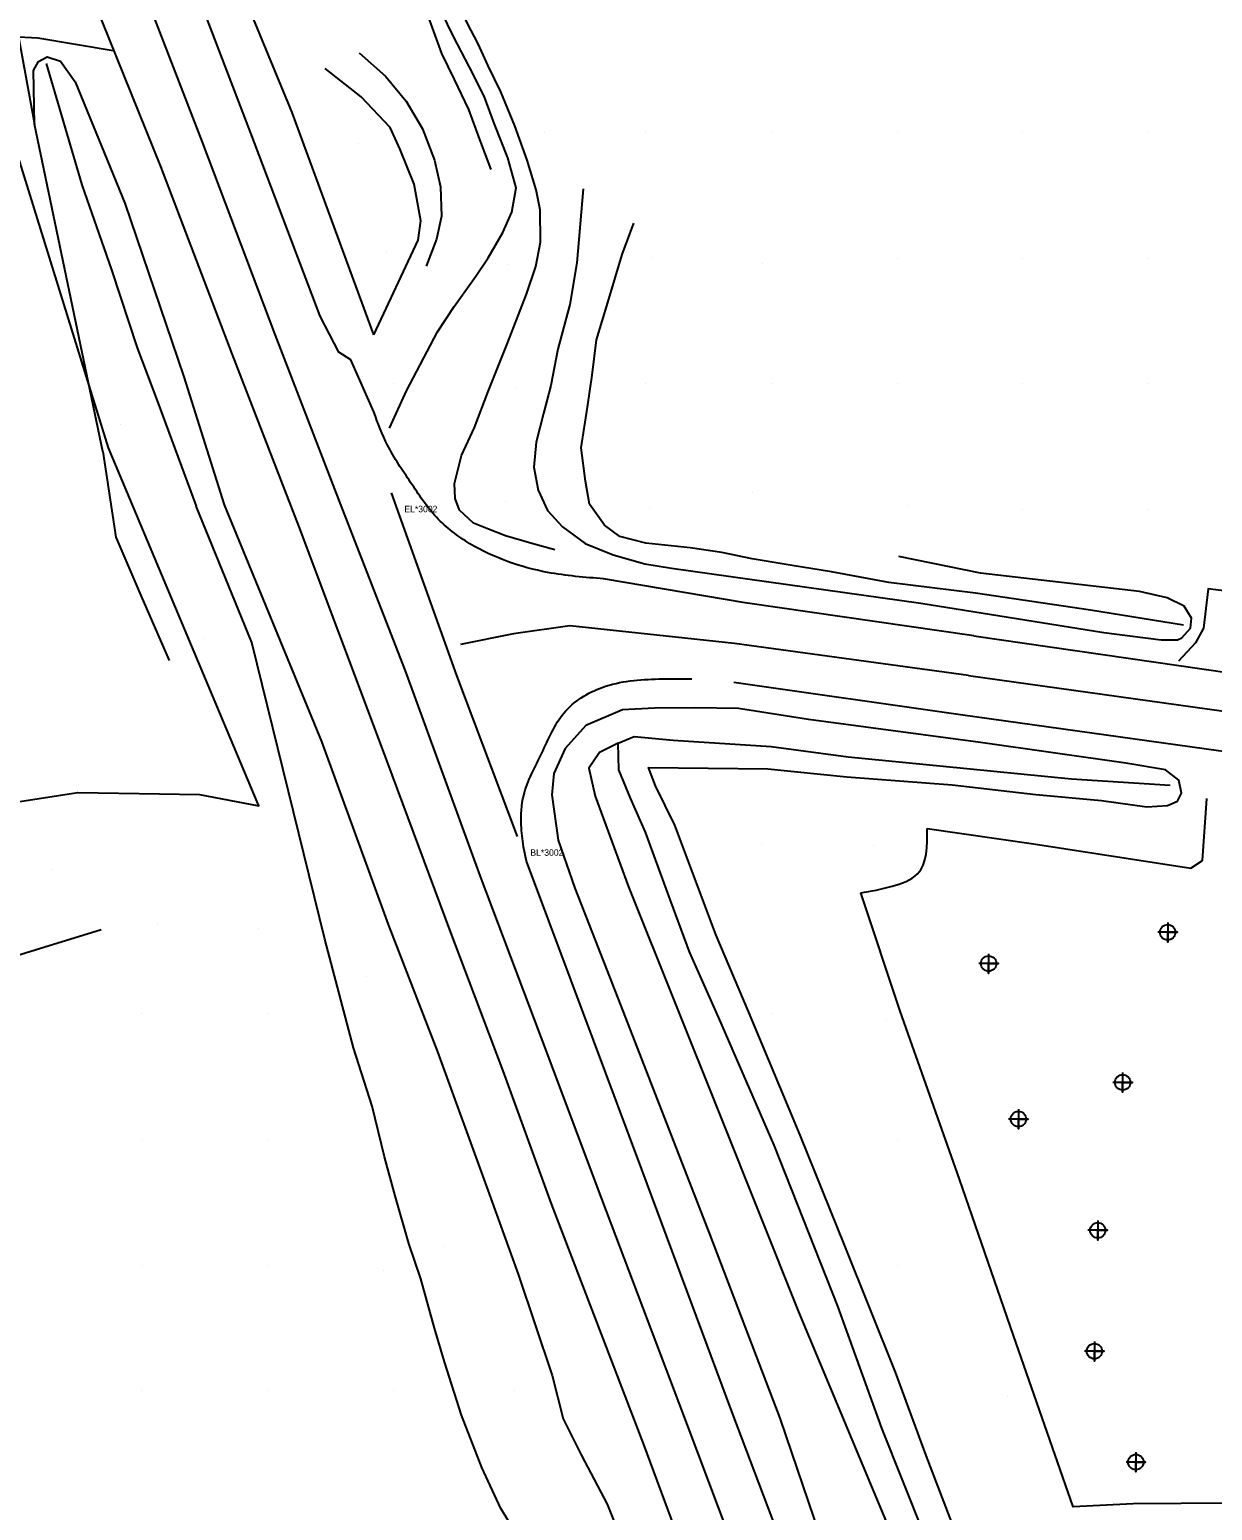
# Model space of a CAD drawing. Extents: x 524772 to 528246, y 273285 to 283088.
# Drawn here: x 527837.2 to 527928.9, y 274106.4 to 274221.1 of the extents above; entities that cross this region are included whole.
import ezdxf

# ---------------------------------------------------------------- set-up
doc = ezdxf.new("R2010")
doc.units = 0
for name, color, linetype in [('Exist DTM Crownline', 7, 'Continuous'), ('Exist DTM Regular Point CELL', 7, 'Continuous'), ('Exist Roads EOP', 7, 'Continuous'), ('Exist Roads EOT', 7, 'Continuous'), ('Exist Roads EOT Cogo Comment', 7, 'Continuous'), ('Old_Level_12', 7, 'Continuous'), ('PH Exist DTM Breakline', 7, 'Continuous'), ('PH Exist DTM Point', 7, 'Continuous')]:
    doc.layers.add(name, color=color, linetype=linetype)

# ---------------------------------------------------------------- blocks, each defined once
blk = doc.blocks.new('EXIST DTM REGULAR POINT')
at = {"layer": 'Exist DTM Regular Point CELL'}
blk.add_lwpolyline([(0, 0.00152), (0, -0.00152), (0, 0), (0.00152, 0), (-0.00152, 0)], dxfattribs=at)
blk.add_circle((0, 0), 0.00119, dxfattribs=at)

msp = doc.modelspace()

# ---------------------------------------------------------------- linework, layer by layer
at = {"layer": 'Exist DTM Crownline'}
for p, q in [((527909.99, 274171.09), (527891.85, 274173.57)), ((527881.22, 274131.5), (527877.32, 274141.9))]:
    msp.add_line(p, q, dxfattribs=at)
for points in [[(527877.32, 274141.9), (527872.16, 274155.51), (527866.36, 274171.44), (527861.32, 274184.4), (527856.24, 274197.5), (527850.61, 274212.41), (527845.36, 274225.99), (527840.1, 274239.58), (527834.55, 274253.77), (527829.3, 274267.02), (527823.63, 274281.27), (527818.21, 274295.07), (527812.62, 274309.15), (527807.09, 274323.12)], [(527891.85, 274173.57), (527879.09, 274174.95), (527874.72, 274174.33), (527870.62, 274173.49)], [(527909.99, 274171.09), (527929.8, 274168.32), (527941.69, 274166.67)], [(527923.71, 274019.28), (527916.64, 274037.99), (527909.48, 274056.66), (527902.42, 274075.37), (527895.35, 274094.08), (527888.28, 274112.79), (527881.22, 274131.5)]]:
    msp.add_lwpolyline(points, dxfattribs=at)
at = {"layer": 'Exist Roads EOP'}
for p, q in [((527892.69, 274176.71), (527881.71, 274178.58)), ((527910.42, 274174.16), (527892.69, 274176.71)), ((527909.57, 274168.02), (527891.81, 274170.56)), ((527884.68, 274132.81), (527880.92, 274142.82)), ((527877.66, 274130.16), (527873.92, 274140.45))]:
    msp.add_line(p, q, dxfattribs=at)
for points in [[(527863.89, 274191.51), (527862.12, 274195.56), (527861.19, 274196.14), (527859.74, 274198.94), (527854.35, 274213.12), (527848.92, 274227.38), (527843.58, 274240.81), (527838, 274255.12), (527832.68, 274268.57), (527827.21, 274282.4), (527821.56, 274296.66), (527815.92, 274310.87), (527810.35, 274324.86), (527804.78, 274338.91), (527799.29, 274352.72), (527793.54, 274366.95), (527787.87, 274381.23), (527782.28, 274395.33), (527776.62, 274409.52), (527770.97, 274423.52), (527765.47, 274437.47), (527760, 274451.08), (527754.4, 274465.08), (527748.73, 274479.07)], [(527873.92, 274140.45), (527869.86, 274151.18), (527864.48, 274165.61), (527858.1, 274182.62), (527852.91, 274196.02), (527847.38, 274210.53), (527841.71, 274224.63), (527836.64, 274238.36), (527831.12, 274252.6), (527825.69, 274266.18), (527820.35, 274279.64), (527814.69, 274293.96), (527808.82, 274308.77), (527803.4, 274322.05)], [(527910.42, 274174.16), (527930.22, 274171.3), (527942.12, 274169.74)], [(527941.29, 274163.79), (527929.37, 274165.25), (527909.57, 274168.02)], [(527906.8, 274159.23), (527915.04, 274158.04), (527927.23, 274156.17), (527928.14, 274156.75), (527928.47, 274161.57)], [(527906.8, 274159.23), (527915.04, 274158.04), (527927.23, 274156.17), (527928.14, 274156.75), (527928.47, 274161.57)], [(527880.92, 274142.82), (527875.74, 274156.69), (527875.5, 274157.82)], [(527945.6, 274107.21), (527933.94, 274106.99), (527922.76, 274106.9), (527918.11, 274106.67), (527913.48, 274119.96), (527909.29, 274132.05), (527904.7, 274145.08), (527901.64, 274154.24)], [(527945.6, 274107.21), (527933.94, 274106.99), (527922.76, 274106.9), (527918.11, 274106.67), (527913.48, 274119.96), (527909.29, 274132.05), (527904.7, 274145.08), (527901.64, 274154.24)], [(527927.17, 274020.59), (527919.92, 274039.22), (527912.85, 274057.93), (527905.78, 274076.65), (527898.72, 274095.36), (527891.65, 274114.07), (527884.68, 274132.81)], [(527920.25, 274017.97), (527912.99, 274036.61), (527906.11, 274055.39), (527898.95, 274074.07), (527891.79, 274092.74), (527884.82, 274111.49), (527877.66, 274130.16)]]:
    msp.add_lwpolyline(points, dxfattribs=at)
for points in [[(527881.71, 274178.58), (527877.37, 274179.08), (527874.25, 274179.93), (527871.35, 274181.3), (527868.75, 274183.35), (527866.75, 274186.05), (527864.96, 274188.94), (527863.89, 274191.51)], [(527875.5, 274157.82), (527875.32, 274159.51), (527875.52, 274161.8), (527876.92, 274165.07), (527878.63, 274168.18), (527881.6, 274170.17), (527885.99, 274170.82), (527888.56, 274170.84)], [(527901.64, 274154.24), (527904.07, 274154.76), (527906.04, 274155.71), (527906.8, 274159.23)], [(527901.64, 274154.24), (527904.07, 274154.76), (527906.04, 274155.71), (527906.8, 274159.23)]]:
    msp.add_spline(points, degree=3, dxfattribs=at)
at = {"layer": 'Exist Roads EOT'}
msp.add_lwpolyline([(527875.03, 274158.62), (527870.34, 274171.09), (527865.26, 274185.24)], dxfattribs=at)
at = {"layer": 'Old_Level_12'}
msp.add_lwpolyline([(527790.41, 274140.76), (527808.09, 274147.58), (527820.7, 274154.72), (527830.77, 274160.45), (527840.94, 274162.02), (527847.27, 274161.91), (527850.38, 274161.86), (527854.98, 274160.99), (527843.32, 274188.73), (527834.36, 274217.55), (527834.17, 274217.65), (527821.77, 274212.77), (527804.33, 274204.71), (527792.62, 274201.51), (527784.15, 274199.26), (527772.83, 274197.49), (527790.39, 274140.96)], dxfattribs=at)
at = {"layer": 'PH Exist DTM Breakline'}
for points in [[(527863.9, 274197.49), (527857.56, 274214.72), (527851.2, 274230.14), (527846, 274240.87), (527842.66, 274248.43), (527840.2, 274254.37)], [(527859.91, 274244.8), (527860.97, 274242.49), (527861.97, 274239.73), (527863.1, 274236.61), (527864.01, 274234.08), (527864.94, 274230.98), (527865.46, 274229.25), (527866.37, 274226.86), (527867.18, 274224.63), (527868.22, 274221.84), (527869.13, 274219.29), (527870.13, 274217.27), (527871.23, 274214.94), (527872.08, 274212.62), (527872.96, 274210.31)], [(527877.94, 274180.84), (527876.15, 274181.32), (527874.1, 274181.91), (527872.78, 274182.42), (527871.63, 274182.89), (527870.55, 274183.89), (527870.19, 274184.81), (527870.14, 274185.98), (527870.68, 274188.13), (527871.69, 274190.31), (527872.75, 274193.09), (527874.27, 274196.83), (527875.72, 274200.64), (527876.46, 274202.77), (527876.83, 274204.67), (527876.78, 274207.16), (527876.48, 274208.72), (527875.78, 274211.02), (527874.83, 274213.69), (527873.74, 274216.31), (527872.77, 274218.34), (527871.99, 274220.04), (527871.15, 274221.61), (527870.13, 274223.79)], [(527865.11, 274190.25), (527866.43, 274193.14), (527868.83, 274197.71), (527870.12, 274199.69), (527871.8, 274202.04), (527872.76, 274203.45), (527873.89, 274205.42), (527874.59, 274207), (527874.94, 274208.88), (527874.29, 274211.2), (527873.24, 274213.8), (527872.44, 274215.98), (527871.3, 274218.24), (527870.08, 274220.6), (527869.13, 274222.51)], [(527836.36, 274220.57), (527837.84, 274220.51), (527843.7, 274219.53)], [(527836.36, 274220.57), (527837.59, 274213.82), (527837.52, 274217.97), (527837.9, 274218.67), (527838.57, 274219.03), (527839.6, 274218.7), (527840.74, 274217.1), (527844.6, 274207.7), (527849.16, 274194.23), (527852.29, 274184.32)], [(527862.75, 274219.33), (527864.79, 274217.52), (527866.41, 274215.6), (527867.68, 274213.45), (527868.6, 274211.01), (527869.07, 274208.96), (527869.13, 274206.68), (527868.76, 274204.91), (527867.95, 274202.81)], [(527838.49, 274218.51), (527841.26, 274209.12), (527843.56, 274202.53), (527845.55, 274196.47), (527847.07, 274192.46), (527850.11, 274184.21)], [(527863.9, 274197.49), (527867.33, 274204.83), (527867.53, 274206.31), (527867.03, 274209.17), (527865.94, 274211.86), (527865.15, 274213.54), (527862.92, 274215.94), (527860.13, 274218.12)], [(527842.89, 274188.45), (527837.59, 274213.82)], [(527880.13, 274208.81), (527879.64, 274203.07), (527879.08, 274199.83), (527878.17, 274196.38), (527877.62, 274193.56), (527877.04, 274191.4), (527876.49, 274189.17), (527876.29, 274187.23), (527876.63, 274185.46), (527877.35, 274183.88), (527878.52, 274182.61), (527880.28, 274181.33), (527882.45, 274180.43), (527884.91, 274179.74), (527886.98, 274179.4), (527906.3, 274176.69), (527920.48, 274174.42), (527924.94, 274173.86), (527926.2, 274173.86), (527926.55, 274174.02), (527927.21, 274174.76), (527927.29, 274175.54), (527926.73, 274176.45), (527925.41, 274177.1), (527923.25, 274177.61), (527910.94, 274179.01), (527904.61, 274180.31)], [(527926.66, 274174.99), (527919.46, 274176.15), (527910.55, 274177.46), (527903.82, 274178.29), (527899.39, 274179.11), (527896.34, 274179.62), (527893.22, 274180.13), (527890.88, 274180.61), (527888.42, 274180.98), (527884.98, 274181.34), (527882.96, 274181.85), (527881.79, 274182.75), (527880.61, 274184.36), (527880.31, 274186.16), (527879.97, 274188.72), (527880.45, 274191.89), (527880.82, 274194.36), (527881.16, 274197.11), (527882.04, 274199.98), (527883.14, 274203.71), (527884.06, 274206.13)], [(527842.89, 274188.45), (527843.9, 274181.8), (527845.84, 274177.29), (527848.04, 274172.25)], [(527888.55, 274069.38), (527880.65, 274092.85), (527878.26, 274099.69), (527877.11, 274101.69), (527875.35, 274103.93), (527873.74, 274106.55), (527872.28, 274109.73), (527870.69, 274113.78), (527869.38, 274117.9), (527868.61, 274120.51), (527867.55, 274124.34), (527866.61, 274127.07), (527865.54, 274130.76), (527864.72, 274133.78), (527863.77, 274137.73), (527862.31, 274142.24), (527860.11, 274150.66), (527854.43, 274173.64), (527850.11, 274184.21)], [(527852.29, 274184.32), (527859.85, 274165.97), (527865.02, 274151.8), (527868.82, 274141.92), (527872.63, 274131.49), (527875.09, 274124.69), (527877.72, 274116.84), (527878.58, 274113.5), (527879.97, 274110.71), (527881.99, 274106.88), (527883.78, 274102.43), (527885.75, 274097.37), (527887.4, 274093.08), (527889.08, 274088.49), (527890.71, 274083.61), (527892.55, 274078.09), (527893.83, 274074.08)], [(527933.53, 274171.12), (527932.31, 274172.45), (527931.54, 274173.72), (527931.43, 274175.19), (527931.58, 274177.41), (527928.57, 274177.81), (527928.22, 274174.77), (527927.6, 274173.63), (527926.29, 274172.2)], [(527920.31, 274161.4), (527923.82, 274160.92), (527925.43, 274161.01), (527926.19, 274161.36), (527926.5, 274161.97), (527926.3, 274162.97), (527925.28, 274163.77), (527922.2, 274164.3), (527910.94, 274165.89), (527897.59, 274167.68), (527892.16, 274168.54), (527888.79, 274168.58), (527885.66, 274168.56), (527883.18, 274168.42), (527880.33, 274167.21), (527878.74, 274165.44), (527877.85, 274163.5), (527877.69, 274161.85), (527878.18, 274158.33), (527879.47, 274154.62), (527883.05, 274145.49), (527889.95, 274127.75), (527895.37, 274113.54), (527899.36, 274101.83)], [(527906.53, 274104.6), (527903.29, 274112.76), (527899.86, 274122.23), (527894.93, 274134.7), (527890.63, 274144.56), (527888.38, 274149.69), (527886.69, 274154.23), (527884.96, 274158.96), (527883.79, 274161.59), (527882.88, 274163.77), (527882.83, 274165.85), (527884.09, 274166.37), (527887.1, 274166.09), (527894.7, 274165.58), (527900.67, 274164.79), (527908.03, 274164.06), (527917.98, 274163.07), (527925.63, 274162.6)], [(527882.83, 274165.85), (527881.38, 274165.13), (527880.56, 274163.92), (527881.05, 274161.74), (527883.64, 274154.71), (527890.78, 274136.91), (527896.81, 274121.78), (527905.08, 274102), (527906.08, 274099.58), (527906.31, 274098.34), (527907.16, 274096.65), (527908.44, 274095.21), (527909.66, 274094.27), (527911.2, 274094.08)], [(527909.04, 274104.58), (527906.72, 274110.66), (527904.34, 274117.11), (527900.42, 274126.9), (527896.94, 274135.47), (527892.94, 274145.06), (527890.41, 274151.03), (527887.22, 274159.49), (527885.73, 274162.53), (527885.19, 274163.97), (527894.45, 274163.85), (527900.56, 274163.24), (527908.74, 274162.61), (527915.21, 274161.86), (527920.31, 274161.4)], [(527788.88, 274132.45), (527821.92, 274144.25), (527829.01, 274147.01), (527833.77, 274148.64), (527837.64, 274149.82), (527842.77, 274151.4)]]:
    msp.add_lwpolyline(points, dxfattribs=at)
at = {"layer": 'PH Exist DTM Point'}
for p, q in [((527862.72, 274212.35), (527862.72, 274212.35)), ((527877.15, 274213.2), (527877.15, 274213.2)), ((527884.95, 274213.19), (527884.95, 274213.19)), ((527894.71, 274213.19), (527894.71, 274213.19)), ((527904.46, 274213.19), (527904.46, 274213.19)), ((527914.22, 274213.19), (527914.22, 274213.19)), ((527923.97, 274213.19), (527923.97, 274213.19)), ((527864.86, 274203.85), (527864.86, 274203.85)), ((527874.24, 274202.95), (527874.24, 274202.95)), ((527885.47, 274203.5), (527885.47, 274203.5)), ((527894.05, 274203.02), (527894.05, 274203.02)), ((527904.46, 274203.44), (527904.46, 274203.44)), ((527914.22, 274203.44), (527914.22, 274203.44)), ((527923.97, 274203.44), (527923.97, 274203.44)), ((527865.45, 274193.69), (527865.45, 274193.69)), ((527874.92, 274193.43), (527874.92, 274193.43)), ((527884.95, 274193.69), (527884.95, 274193.69)), ((527894.71, 274193.69), (527894.71, 274193.69)), ((527904.46, 274193.69), (527904.46, 274193.69)), ((527914.22, 274193.69), (527914.22, 274193.69)), ((527923.97, 274193.69), (527923.97, 274193.69)), ((527844.28, 274190.56), (527844.28, 274190.56)), ((527874.14, 274184.61), (527874.14, 274184.61)), ((527893.27, 274185.3), (527893.27, 274185.3)), ((527885.23, 274184.09), (527885.23, 274184.09)), ((527905.27, 274184.26), (527905.27, 274184.26)), ((527914.22, 274183.93), (527914.22, 274183.93)), ((527923.97, 274183.93), (527923.97, 274183.93)), ((527850.66, 274173.94), (527850.66, 274173.94)), ((527893.92, 274157.99), (527893.92, 274157.99)), ((527902.65, 274157.94), (527902.65, 274157.94)), ((527838.92, 274156.05), (527838.92, 274156.05)), ((527847.12, 274151.76), (527847.12, 274151.76)), ((527854.94, 274151.51), (527854.94, 274151.51)), ((527863.3, 274147.77), (527863.3, 274147.77)), ((527845.92, 274144.93), (527845.92, 274144.93)), ((527855.69, 274144.92), (527855.69, 274144.92)), ((527894.71, 274144.92), (527894.71, 274144.92)), ((527903.61, 274144.34), (527903.61, 274144.34)), ((527845.96, 274135.15), (527845.96, 274135.15)), ((527855.69, 274135.16), (527855.69, 274135.16)), ((527904.46, 274135.16), (527904.46, 274135.16)), ((527869.4, 274126.87), (527869.4, 274126.87)), ((527845.94, 274125.41), (527845.94, 274125.41)), ((527855.69, 274125.41), (527855.69, 274125.41)), ((527864.67, 274124.99), (527864.67, 274124.99)), ((527904.46, 274125.41), (527904.46, 274125.41)), ((527874.82, 274115.69), (527874.82, 274115.69)), ((527845.92, 274115.67), (527845.92, 274115.67)), ((527855.69, 274115.66), (527855.69, 274115.66)), ((527865.45, 274115.66), (527865.45, 274115.66)), ((527913.05, 274115.19), (527913.05, 274115.19))]:
    msp.add_line(p, q, dxfattribs=at)

# ---------------------------------------------------------------- block references
at = {"layer": 'Exist DTM Regular Point CELL', "xscale": 500, "yscale": 500}
for p in [(527925.44, 274151.19), (527911.56, 274148.77), (527921.95, 274139.56), (527913.87, 274136.72), (527920.02, 274128.1), (527919.76, 274118.73), (527922.97, 274110.14)]:
    msp.add_blockref('EXIST DTM REGULAR POINT', p, dxfattribs=at)

# ---------------------------------------------------------------- texts
at = {"layer": 'Exist Roads EOT Cogo Comment'}
for s, p in [('EL*3002', (527866.26, 274183.74)), ('BL*3002', (527876.03, 274157.12))]:
    msp.add_text(s, height=0.5, dxfattribs=at).set_placement(p)

doc.saveas('drawing.dxf')
